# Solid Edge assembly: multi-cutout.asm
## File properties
Author: Robert a Rhodes jr
Template: Normal.asm
Last saved by: Cadcim
Revision: 9
Application: Solid Edge
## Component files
multi-1-plate.par
multi-2-plate.par
multi-3.par
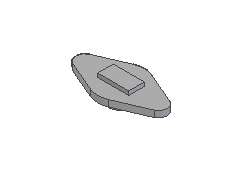
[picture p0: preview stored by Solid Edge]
